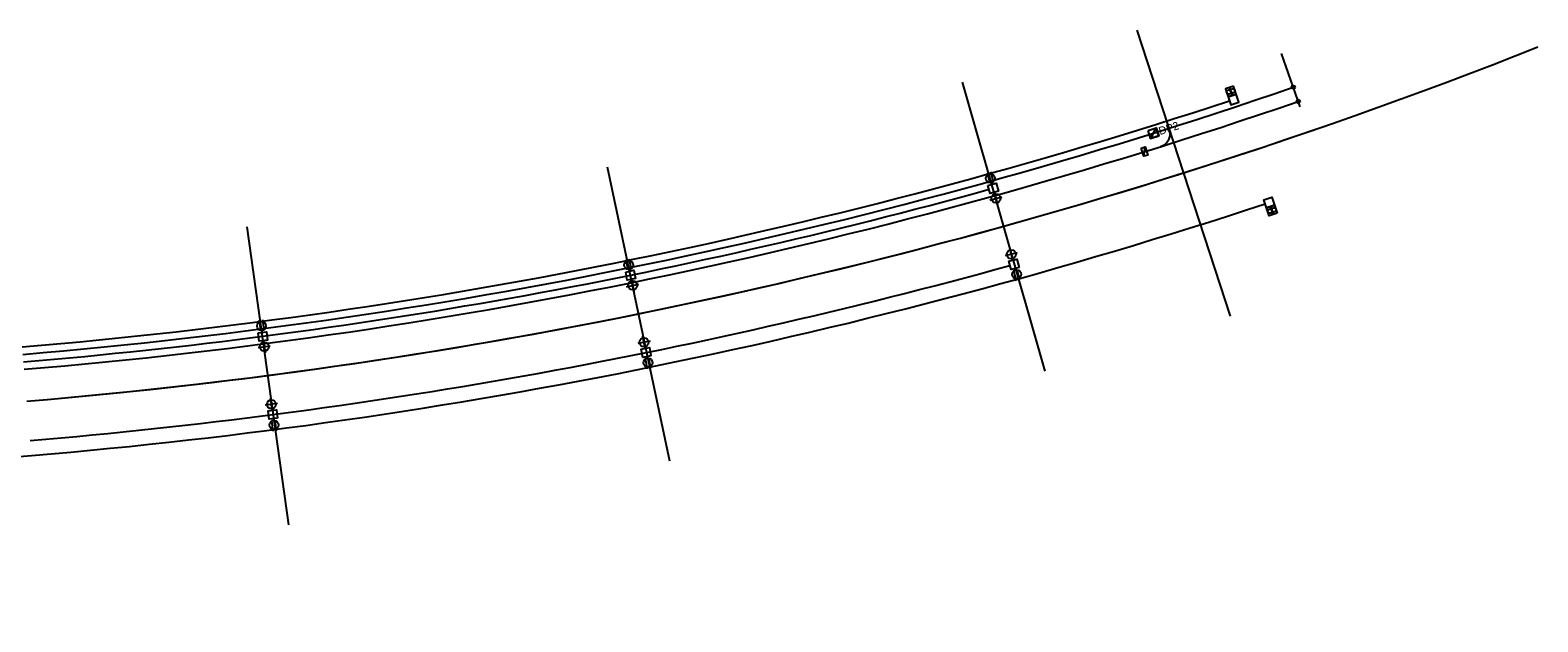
# Model space of a CAD drawing. Extents: x 927222 to 928611, y 636651 to 637029.
# Drawn here: x 928410.4 to 928611.1, y 636764.2 to 636842.9 of the extents above; entities that cross this region are included whole.
import ezdxf

# ---------------------------------------------------------------- set-up
doc = ezdxf.new("R2010")
doc.units = 0
for name, color, linetype in [('Miscellaneous2', 7, 'Continuous'), ('NonPlottingEle_dp', 7, 'Continuous'), ('PoleLight', 7, 'Continuous'), ('TextLabel', 7, 'Continuous')]:
    doc.layers.add(name, color=color, linetype=linetype)

msp = doc.modelspace()

# ---------------------------------------------------------------- linework, layer by layer
at = {"layer": 'Miscellaneous2'}
for p, q in [((928570.19, 636804.84), (928557.8, 636842.87)), ((928579.47, 636832.69), (928577.01, 636839.77)), ((928545.54, 636797.53), (928534.51, 636835.97)), ((928495.56, 636785.53), (928487.27, 636824.66)), ((928444.85, 636777.1), (928439.34, 636816.72))]:
    msp.add_line(p, q, dxfattribs=at)
for end in [291.57718, 289.02547]:
    msp.add_arc((928350.92, 637498.56), 707.5, 274.79003, end, dxfattribs=at)
at = {"layer": 'NonPlottingEle_dp'}
msp.add_line((928146.59, 636764.18), (928410.61, 636786.31), dxfattribs=at)
for centre, radius, start, end in [((928350.92, 637498.56), 701.25, 274.79003, 288.94268), ((928350.92, 637498.56), 700.25, 274.79003, 288.23668), ((928350.92, 637498.56), 703.25, 274.79003, 288.94327), ((928560.33, 636829.16), 1.85, 287.3718, 5.548), ((928350.92, 637498.56), 702.25, 274.79003, 285.45574), ((928350.92, 637498.56), 714.75, 274.79003, 288.25514), ((928350.92, 637498.56), 712.75, 274.79003, 285.4538)]:
    msp.add_arc(centre, radius, start, end, dxfattribs=at)
at = {"layer": 'PoleLight'}
for p, q in [((928537.81, 636823.9), (928538.17, 636822.58)), ((928538.24, 636824.02), (928538.61, 636822.7)), ((928538.46, 636822.38), (928538.4, 636822.6)), ((928538.76, 636821.29), (928539.2, 636819.71)), ((928538.19, 636820.28), (928539.78, 636820.72)), ((928541.82, 636813.28), (928540.23, 636812.85)), ((928541.24, 636812.27), (928540.81, 636813.86)), ((928489.7, 636812.39), (928489.97, 636811.04)), ((928490.14, 636812.48), (928490.42, 636811.13)), ((928490.25, 636810.82), (928490.2, 636811.04)), ((928541.53, 636811.19), (928541.59, 636810.97)), ((928542.18, 636809.66), (928541.82, 636810.99)), ((928489.83, 636808.75), (928491.44, 636809.08)), ((928490.47, 636809.72), (928490.8, 636808.11)), ((928541.74, 636809.54), (928541.38, 636810.87)), ((928440.9, 636804.3), (928441.08, 636802.94)), ((928441.34, 636802.7), (928441.31, 636802.93)), ((928441.35, 636804.36), (928441.53, 636803)), ((928440.77, 636800.67), (928442.4, 636800.88)), ((928441.48, 636801.59), (928441.7, 636799.96)), ((928492.95, 636801.51), (928491.34, 636801.2)), ((928492.3, 636800.55), (928491.99, 636802.16)), ((928492.61, 636797.79), (928492.35, 636799.14)), ((928492.52, 636799.44), (928492.56, 636799.22)), ((928493.05, 636797.87), (928492.79, 636799.22)), ((928443.37, 636793.22), (928441.74, 636793.02)), ((928442.66, 636792.31), (928442.46, 636793.94)), ((928442.78, 636789.53), (928442.61, 636790.9)), ((928442.8, 636791.19), (928442.83, 636790.97)), ((928443.22, 636789.59), (928443.05, 636790.95))]:
    msp.add_line(p, q, dxfattribs=at)
for centre, radius in [((928578.56, 636835.29), 0.236), ((928579.22, 636833.4), 0.236), ((928538.24, 636823.17), 0.597), ((928538.98, 636820.5), 0.597), ((928541.02, 636813.07), 0.597), ((928490.09, 636811.63), 0.597), ((928541.74, 636810.39), 0.597), ((928490.64, 636808.92), 0.597), ((928441.23, 636803.52), 0.597), ((928441.59, 636800.77), 0.597), ((928492.14, 636801.35), 0.597), ((928492.68, 636798.64), 0.597), ((928442.56, 636793.12), 0.597), ((928442.9, 636790.37), 0.597)]:
    msp.add_circle(centre, radius, dxfattribs=at)
at = {"layer": 'TextLabel'}
for p, q in [((928559.57, 636828.48), (928560.31, 636829.89)), ((928560.31, 636829.89), (928559.57, 636828.48)), ((928558.65, 636826.1), (928558.86, 636827.34))]:
    msp.add_line(p, q, dxfattribs=at)
for points in [[(928570.07, 636835.26), (928569.53, 636835.09), (928569.88, 636834.02), (928570.42, 636834.19)], [(928570.6, 636835.44), (928570.07, 636835.26), (928570.42, 636834.19), (928570.95, 636834.37)], [(928570.95, 636834.37), (928569.88, 636834.02), (928570.24, 636832.95), (928571.3, 636833.3)], [(928559.23, 636829.55), (928560.31, 636829.89), (928560.64, 636828.82), (928559.57, 636828.48)], [(928558.32, 636827.18), (928558.86, 636827.34), (928559.19, 636826.27), (928558.65, 636826.1)], [(928537.92, 636822.23), (928539.01, 636822.53), (928539.31, 636821.45), (928538.22, 636821.14)], [(928576.06, 636819.6), (928574.99, 636819.25), (928574.64, 636820.32), (928575.71, 636820.67)], [(928575.88, 636818.36), (928575.35, 636818.18), (928574.99, 636819.25), (928575.53, 636819.43)], [(928576.41, 636818.53), (928575.88, 636818.36), (928575.53, 636819.43), (928576.06, 636819.6)], [(928489.7, 636810.71), (928490.8, 636810.94), (928491.02, 636809.83), (928489.92, 636809.61)], [(928542.07, 636811.33), (928540.99, 636811.04), (928540.69, 636812.13), (928541.78, 636812.42)], [(928440.78, 636802.63), (928441.9, 636802.77), (928442.04, 636801.66), (928440.93, 636801.51)], [(928493.07, 636799.55), (928491.97, 636799.33), (928491.75, 636800.44), (928492.85, 636800.66)], [(928443.36, 636791.26), (928442.24, 636791.12), (928442.1, 636792.24), (928443.22, 636792.38)]]:
    msp.add_lwpolyline(points, close=True, dxfattribs=at)
msp.add_lwpolyline([(928559.57, 636828.48), (928560.64, 636828.82), (928560.31, 636829.89)], dxfattribs=at)
for centre in [(928570.51, 636834.82), (928569.97, 636834.64), (928575.44, 636818.8), (928575.97, 636818.98)]:
    msp.add_circle(centre, 0.281, dxfattribs=at)

# ---------------------------------------------------------------- texts
msp.add_text('DP2', height=1.05, rotation=17.46, dxfattribs=at).set_placement((928560.83, 636828.92))

doc.saveas('drawing.dxf')
